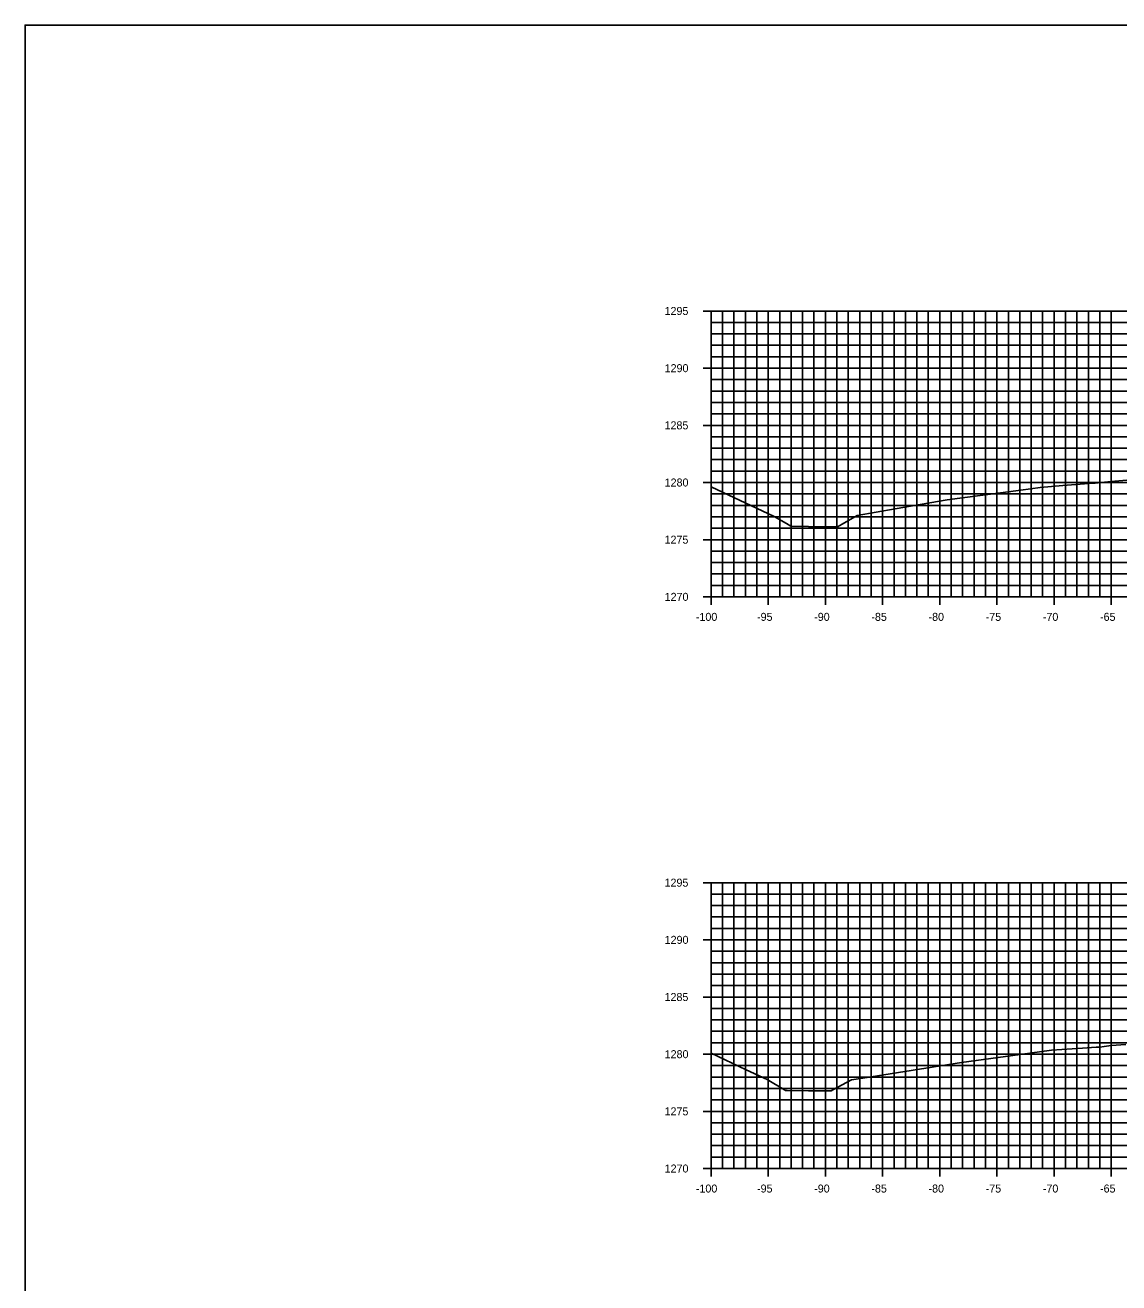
# Model space of a CAD drawing. Extents: x 674939 to 678919, y 750652 to 765176.
# Drawn here: x 678578.5 to 678674.2, y 755862.6 to 755972.6 of the extents above; entities that cross this region are included whole.
import ezdxf

# ---------------------------------------------------------------- set-up
doc = ezdxf.new("R2010")
doc.units = 0
for name, color, linetype in [('R_Axis', 7, 'Continuous'), ('R_Axis Annot', 7, 'Continuous'), ('R_Exist Surface', 7, 'Continuous'), ('R_Grid', 7, 'Continuous'), ('R_No Plot', 7, 'Continuous')]:
    doc.layers.add(name, color=color, linetype=linetype)

msp = doc.modelspace()

# ---------------------------------------------------------------- linework, layer by layer
at = {"layer": 'R_Axis'}
for p, q in [((678637.83, 755947.55), (678639.23, 755947.55)), ((678638.53, 755922.55), (678638.53, 755947.55)), ((678638.53, 755946.55), (678638.88, 755946.55)), ((678638.53, 755945.55), (678638.88, 755945.55)), ((678638.53, 755944.55), (678638.88, 755944.55)), ((678638.53, 755943.55), (678638.88, 755943.55)), ((678637.83, 755942.55), (678639.23, 755942.55)), ((678638.53, 755941.55), (678638.88, 755941.55)), ((678638.53, 755940.55), (678638.88, 755940.55)), ((678638.53, 755939.55), (678638.88, 755939.55)), ((678638.53, 755938.55), (678638.88, 755938.55)), ((678637.83, 755937.55), (678639.23, 755937.55)), ((678638.53, 755936.55), (678638.88, 755936.55)), ((678638.53, 755935.55), (678638.88, 755935.55)), ((678638.53, 755934.55), (678638.88, 755934.55)), ((678638.53, 755933.55), (678638.88, 755933.55)), ((678637.83, 755932.55), (678639.23, 755932.55)), ((678638.53, 755931.55), (678638.88, 755931.55)), ((678638.53, 755930.55), (678638.88, 755930.55)), ((678638.53, 755929.55), (678638.88, 755929.55)), ((678638.53, 755928.55), (678638.88, 755928.55)), ((678637.83, 755927.55), (678639.23, 755927.55)), ((678638.53, 755926.55), (678638.88, 755926.55)), ((678638.53, 755925.55), (678638.88, 755925.55)), ((678638.53, 755924.55), (678638.88, 755924.55)), ((678638.53, 755923.55), (678638.88, 755923.55)), ((678637.83, 755922.55), (678639.23, 755922.55)), ((678638.53, 755921.85), (678638.53, 755923.25)), ((678638.53, 755922.55), (678838.53, 755922.55)), ((678643.53, 755921.85), (678643.53, 755923.25)), ((678648.53, 755921.85), (678648.53, 755923.25)), ((678653.53, 755921.85), (678653.53, 755923.25)), ((678658.53, 755921.85), (678658.53, 755923.25)), ((678663.53, 755921.85), (678663.53, 755923.25)), ((678668.53, 755921.85), (678668.53, 755923.25)), ((678673.53, 755921.85), (678673.53, 755923.25)), ((678637.83, 755897.55), (678639.23, 755897.55)), ((678638.53, 755872.55), (678638.53, 755897.55)), ((678638.53, 755896.55), (678638.88, 755896.55)), ((678638.53, 755895.55), (678638.88, 755895.55)), ((678638.53, 755894.55), (678638.88, 755894.55)), ((678637.83, 755892.55), (678639.23, 755892.55)), ((678638.53, 755893.55), (678638.88, 755893.55)), ((678638.53, 755891.55), (678638.88, 755891.55)), ((678638.53, 755890.55), (678638.88, 755890.55)), ((678638.53, 755889.55), (678638.88, 755889.55)), ((678638.53, 755888.55), (678638.88, 755888.55)), ((678637.83, 755887.55), (678639.23, 755887.55)), ((678638.53, 755886.55), (678638.88, 755886.55)), ((678638.53, 755885.55), (678638.88, 755885.55)), ((678638.53, 755884.55), (678638.88, 755884.55)), ((678638.53, 755883.55), (678638.88, 755883.55)), ((678637.83, 755882.55), (678639.23, 755882.55)), ((678638.53, 755881.55), (678638.88, 755881.55)), ((678638.53, 755880.55), (678638.88, 755880.55)), ((678638.53, 755879.55), (678638.88, 755879.55)), ((678638.53, 755878.55), (678638.88, 755878.55)), ((678637.83, 755877.55), (678639.23, 755877.55)), ((678638.53, 755876.55), (678638.88, 755876.55)), ((678638.53, 755875.55), (678638.88, 755875.55)), ((678638.53, 755874.55), (678638.88, 755874.55)), ((678638.53, 755873.55), (678638.88, 755873.55)), ((678638.53, 755871.85), (678638.53, 755873.25)), ((678643.53, 755871.85), (678643.53, 755873.25)), ((678648.53, 755871.85), (678648.53, 755873.25)), ((678653.53, 755871.85), (678653.53, 755873.25)), ((678658.53, 755871.85), (678658.53, 755873.25)), ((678663.53, 755871.85), (678663.53, 755873.25)), ((678668.53, 755871.85), (678668.53, 755873.25)), ((678673.53, 755871.85), (678673.53, 755873.25)), ((678637.83, 755872.55), (678639.23, 755872.55)), ((678638.53, 755872.55), (678838.53, 755872.55))]:
    msp.add_line(p, q, dxfattribs=at)
at = {"layer": 'R_Exist Surface'}
for points in [[(678638.53, 755932.18), (678644.04, 755929.59), (678645.12, 755928.96), (678645.51, 755928.72), (678647.04, 755928.69), (678647.58, 755928.67), (678649.08, 755928.67), (678649.58, 755928.66), (678649.99, 755928.9), (678651.3, 755929.65), (678654.64, 755930.25), (678659.17, 755931.03), (678665.61, 755931.88), (678667.31, 755932.11), (678669.3, 755932.28), (678671.96, 755932.5), (678672.12, 755932.49), (678673.5, 755932.63), (678674.89, 755932.75)], [(678638.53, 755882.64), (678641.59, 755881.19), (678643.44, 755880.33), (678644.94, 755879.44), (678645.05, 755879.38), (678645.19, 755879.37), (678647.05, 755879.34), (678648.87, 755879.34), (678649.03, 755879.34), (678649.17, 755879.42), (678650.82, 755880.31), (678651.79, 755880.46), (678660.43, 755881.82), (678665.57, 755882.52), (678668.3, 755882.89), (678671.03, 755883.09), (678672.21, 755883.17), (678672.52, 755883.17), (678672.91, 755883.22), (678673.51, 755883.31), (678674.82, 755883.41)]]:
    msp.add_lwpolyline(points, dxfattribs=at)
at = {"layer": 'R_Grid'}
for p, q in [((678638.53, 755947.55), (678838.53, 755947.55)), ((678638.53, 755922.55), (678638.53, 755947.55)), ((678639.53, 755922.55), (678639.53, 755947.55)), ((678640.53, 755922.55), (678640.53, 755947.55)), ((678641.53, 755922.55), (678641.53, 755947.55)), ((678642.53, 755922.55), (678642.53, 755947.55)), ((678643.53, 755922.55), (678643.53, 755947.55)), ((678644.53, 755922.55), (678644.53, 755947.55)), ((678645.53, 755922.55), (678645.53, 755947.55)), ((678646.53, 755922.55), (678646.53, 755947.55)), ((678647.53, 755922.55), (678647.53, 755947.55)), ((678648.53, 755922.55), (678648.53, 755947.55)), ((678649.53, 755922.55), (678649.53, 755947.55)), ((678650.53, 755922.55), (678650.53, 755947.55)), ((678651.53, 755922.55), (678651.53, 755947.55)), ((678652.53, 755922.55), (678652.53, 755947.55)), ((678653.53, 755922.55), (678653.53, 755947.55)), ((678654.53, 755922.55), (678654.53, 755947.55)), ((678655.53, 755922.55), (678655.53, 755947.55)), ((678656.53, 755922.55), (678656.53, 755947.55)), ((678657.53, 755922.55), (678657.53, 755947.55)), ((678658.53, 755922.55), (678658.53, 755947.55)), ((678659.53, 755922.55), (678659.53, 755947.55)), ((678660.53, 755922.55), (678660.53, 755947.55)), ((678661.53, 755922.55), (678661.53, 755947.55)), ((678662.53, 755922.55), (678662.53, 755947.55)), ((678663.53, 755922.55), (678663.53, 755947.55)), ((678664.53, 755922.55), (678664.53, 755947.55)), ((678665.53, 755922.55), (678665.53, 755947.55)), ((678666.53, 755922.55), (678666.53, 755947.55)), ((678667.53, 755922.55), (678667.53, 755947.55)), ((678668.53, 755922.55), (678668.53, 755947.55)), ((678669.53, 755922.55), (678669.53, 755947.55)), ((678670.53, 755922.55), (678670.53, 755947.55)), ((678671.53, 755922.55), (678671.53, 755947.55)), ((678672.53, 755922.55), (678672.53, 755947.55)), ((678673.53, 755922.55), (678673.53, 755947.55)), ((678638.53, 755946.55), (678838.53, 755946.55)), ((678638.53, 755945.55), (678838.53, 755945.55)), ((678638.53, 755944.55), (678838.53, 755944.55)), ((678638.53, 755943.55), (678838.53, 755943.55)), ((678638.53, 755942.55), (678838.53, 755942.55)), ((678638.53, 755941.55), (678838.53, 755941.55)), ((678638.53, 755940.55), (678838.53, 755940.55)), ((678638.53, 755939.55), (678838.53, 755939.55)), ((678638.53, 755938.55), (678838.53, 755938.55)), ((678638.53, 755937.55), (678838.53, 755937.55)), ((678638.53, 755936.55), (678838.53, 755936.55)), ((678638.53, 755935.55), (678838.53, 755935.55)), ((678638.53, 755934.55), (678838.53, 755934.55)), ((678638.53, 755933.55), (678838.53, 755933.55)), ((678638.53, 755932.55), (678838.53, 755932.55)), ((678638.53, 755931.55), (678838.53, 755931.55)), ((678638.53, 755930.55), (678838.53, 755930.55)), ((678638.53, 755929.55), (678838.53, 755929.55)), ((678638.53, 755928.55), (678838.53, 755928.55)), ((678638.53, 755927.55), (678838.53, 755927.55)), ((678638.53, 755926.55), (678838.53, 755926.55)), ((678638.53, 755925.55), (678838.53, 755925.55)), ((678638.53, 755924.55), (678838.53, 755924.55)), ((678638.53, 755923.55), (678838.53, 755923.55)), ((678638.53, 755922.55), (678838.53, 755922.55)), ((678638.53, 755897.55), (678838.53, 755897.55)), ((678638.53, 755872.55), (678638.53, 755897.55)), ((678639.53, 755872.55), (678639.53, 755897.55)), ((678640.53, 755872.55), (678640.53, 755897.55)), ((678641.53, 755872.55), (678641.53, 755897.55)), ((678642.53, 755872.55), (678642.53, 755897.55)), ((678643.53, 755872.55), (678643.53, 755897.55)), ((678644.53, 755872.55), (678644.53, 755897.55)), ((678645.53, 755872.55), (678645.53, 755897.55)), ((678646.53, 755872.55), (678646.53, 755897.55)), ((678647.53, 755872.55), (678647.53, 755897.55)), ((678648.53, 755872.55), (678648.53, 755897.55)), ((678649.53, 755872.55), (678649.53, 755897.55)), ((678650.53, 755872.55), (678650.53, 755897.55)), ((678651.53, 755872.55), (678651.53, 755897.55)), ((678652.53, 755872.55), (678652.53, 755897.55)), ((678653.53, 755872.55), (678653.53, 755897.55)), ((678654.53, 755872.55), (678654.53, 755897.55)), ((678655.53, 755872.55), (678655.53, 755897.55)), ((678656.53, 755872.55), (678656.53, 755897.55)), ((678657.53, 755872.55), (678657.53, 755897.55)), ((678658.53, 755872.55), (678658.53, 755897.55)), ((678659.53, 755872.55), (678659.53, 755897.55)), ((678660.53, 755872.55), (678660.53, 755897.55)), ((678661.53, 755872.55), (678661.53, 755897.55)), ((678662.53, 755872.55), (678662.53, 755897.55)), ((678663.53, 755872.55), (678663.53, 755897.55)), ((678664.53, 755872.55), (678664.53, 755897.55)), ((678665.53, 755872.55), (678665.53, 755897.55)), ((678666.53, 755872.55), (678666.53, 755897.55)), ((678667.53, 755872.55), (678667.53, 755897.55)), ((678668.53, 755872.55), (678668.53, 755897.55)), ((678669.53, 755872.55), (678669.53, 755897.55)), ((678670.53, 755872.55), (678670.53, 755897.55)), ((678671.53, 755872.55), (678671.53, 755897.55)), ((678672.53, 755872.55), (678672.53, 755897.55)), ((678673.53, 755872.55), (678673.53, 755897.55)), ((678638.53, 755896.55), (678838.53, 755896.55)), ((678638.53, 755895.55), (678838.53, 755895.55)), ((678638.53, 755894.55), (678838.53, 755894.55)), ((678638.53, 755893.55), (678838.53, 755893.55)), ((678638.53, 755892.55), (678838.53, 755892.55)), ((678638.53, 755891.55), (678838.53, 755891.55)), ((678638.53, 755890.55), (678838.53, 755890.55)), ((678638.53, 755889.55), (678838.53, 755889.55)), ((678638.53, 755888.55), (678838.53, 755888.55)), ((678638.53, 755887.55), (678838.53, 755887.55)), ((678638.53, 755886.55), (678838.53, 755886.55)), ((678638.53, 755885.55), (678838.53, 755885.55)), ((678638.53, 755884.55), (678838.53, 755884.55)), ((678638.53, 755883.55), (678838.53, 755883.55)), ((678638.53, 755882.55), (678838.53, 755882.55)), ((678638.53, 755881.55), (678838.53, 755881.55)), ((678638.53, 755880.55), (678838.53, 755880.55)), ((678638.53, 755879.55), (678838.53, 755879.55)), ((678638.53, 755878.55), (678838.53, 755878.55)), ((678638.53, 755877.55), (678838.53, 755877.55)), ((678638.53, 755876.55), (678838.53, 755876.55)), ((678638.53, 755875.55), (678838.53, 755875.55)), ((678638.53, 755874.55), (678838.53, 755874.55)), ((678638.53, 755873.55), (678838.53, 755873.55)), ((678638.53, 755872.55), (678838.53, 755872.55))]:
    msp.add_line(p, q, dxfattribs=at)
at = {"layer": 'R_No Plot'}
msp.add_lwpolyline([(678578.53, 755752.55), (678918.53, 755752.55), (678918.53, 755972.55), (678578.53, 755972.55)], close=True, dxfattribs=at)

# ---------------------------------------------------------------- texts
at = {"layer": 'R_Axis Annot'}
for s, p in [('1295', (678634.46, 755947.2)), ('1290', (678634.47, 755942.2)), ('1285', (678634.46, 755937.2)), ('1280', (678634.47, 755932.2)), ('1275', (678634.46, 755927.2)), ('1270', (678634.47, 755922.2)), ('-100', (678637.2, 755920.45)), ('-95', (678642.55, 755920.45)), ('-90', (678647.55, 755920.45)), ('-85', (678652.55, 755920.45)), ('-80', (678657.55, 755920.45)), ('-75', (678662.55, 755920.45)), ('-70', (678667.55, 755920.45)), ('-65', (678672.55, 755920.45)), ('1295', (678634.46, 755897.2)), ('1290', (678634.47, 755892.2)), ('1285', (678634.46, 755887.2)), ('1280', (678634.47, 755882.2)), ('1275', (678634.46, 755877.2)), ('1270', (678634.47, 755872.2)), ('-100', (678637.2, 755870.45)), ('-95', (678642.55, 755870.45)), ('-90', (678647.55, 755870.45)), ('-85', (678652.55, 755870.45)), ('-80', (678657.55, 755870.45)), ('-75', (678662.55, 755870.45)), ('-70', (678667.55, 755870.45)), ('-65', (678672.55, 755870.45))]:
    msp.add_text(s, height=0.7, dxfattribs=at).set_placement(p)

doc.saveas('drawing.dxf')
